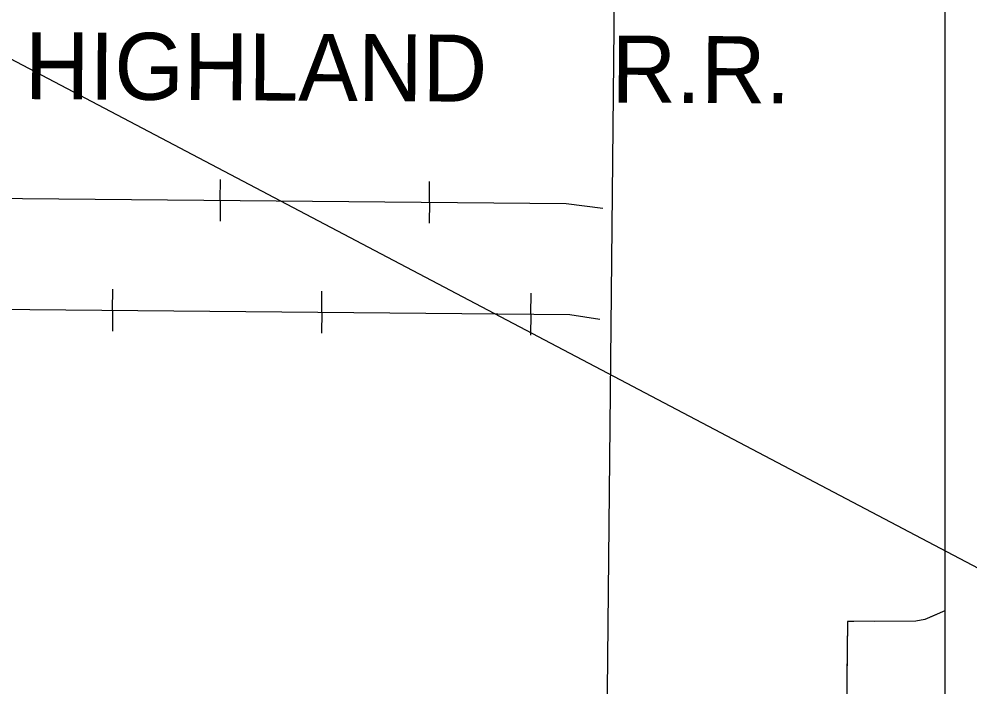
# Model space of a CAD drawing. Extents: x 1373094 to 1376427, y 1168361 to 1170494.
# Drawn here: x 1373883.2 to 1373983.1, y 1169997.1 to 1170067.3 of the extents above; entities that cross this region are included whole.
import ezdxf

# ---------------------------------------------------------------- set-up
doc = ezdxf.new("R2010")
doc.units = 0
for name, color, linetype in [('R_Axis', 7, 'Continuous'), ('R_Draft', 7, 'Continuous'), ('R_No Plot', 7, 'Continuous')]:
    doc.layers.add(name, color=color, linetype=linetype)

msp = doc.modelspace()

# ---------------------------------------------------------------- linework, layer by layer
at = {"layer": 'R_Axis'}
for p, q in [((1373904.365, 1170048.253), (1373904.386, 1170050.453)), ((1373926.364, 1170048.042), (1373926.385, 1170050.242)), ((1373904.365, 1170048.253), (1373904.344, 1170046.053)), ((1373926.364, 1170048.042), (1373926.343, 1170045.842)), ((1373893.035, 1170036.699), (1373893.056, 1170038.898)), ((1373915.034, 1170036.489), (1373915.055, 1170038.689)), ((1373937.033, 1170036.28), (1373937.054, 1170038.48)), ((1373893.035, 1170036.699), (1373893.014, 1170034.499)), ((1373915.034, 1170036.489), (1373915.013, 1170034.289)), ((1373937.033, 1170036.28), (1373937.012, 1170034.08))]:
    msp.add_line(p, q, dxfattribs=at)
for points in [[(1373945.823, 1170073.361), (1373945.043, 1169993.171), (1373944.352, 1169904.477), (1373944.122, 1169861.542)], [(1373875.9, 1170048.527), (1373940.758, 1170047.903), (1373944.604, 1170047.416)], [(1373875.9, 1170048.527), (1373940.758, 1170047.903), (1373944.604, 1170047.416)], [(1373872.22, 1170037.279), (1373872.668, 1170037.171), (1373873.463, 1170037.021), (1373874.319, 1170036.906), (1373875.158, 1170036.854), (1373875.949, 1170036.839), (1373884.32, 1170036.781), (1373941.124, 1170036.241), (1373944.304, 1170035.74)], [(1373875.949, 1170036.839), (1373884.32, 1170036.781), (1373941.124, 1170036.241), (1373944.304, 1170035.74)], [(1373980.591, 1170005.075), (1373978.49, 1170004.159), (1373977.56, 1170004.006), (1373970.358, 1170003.954), (1373969.77, 1169950.858), (1373969.654, 1169944.268), (1373960.216, 1169919.492), (1373951.262, 1169896.13), (1373950.813, 1169895.385), (1373950.44, 1169894.892), (1373950.182, 1169894.535), (1373949.759, 1169894.058), (1373949.416, 1169893.75), (1373948.876, 1169893.304), (1373895.645, 1169861.535), (1373894.122, 1169861.034), (1373893.46, 1169860.82), (1373892.345, 1169860.746)], [(1373979.704, 1170004.689), (1373978.49, 1170004.159), (1373977.56, 1170004.006), (1373973.227, 1170003.975)], [(1373971.027, 1170003.959), (1373970.358, 1170003.954), (1373970.292, 1169998.024)]]:
    msp.add_lwpolyline(points, dxfattribs=at)
at = {"layer": 'R_Draft'}
msp.add_line((1373526.317, 1170250.361), (1374006.355, 1169997.871), dxfattribs=at)
at = {"layer": 'R_No Plot'}
msp.add_lwpolyline([(1373251.191, 1170420.714), (1373980.591, 1170420.714), (1373980.591, 1169636.224), (1373251.191, 1169636.224)], close=True, dxfattribs=at)

# ---------------------------------------------------------------- texts
at = {"layer": 'R_Axis'}
msp.add_text('HIGHLAND     R.R.', height=7.04002, rotation=359.67145, dxfattribs=at).set_placement((1373883.782, 1170058.895))

doc.saveas('drawing.dxf')
